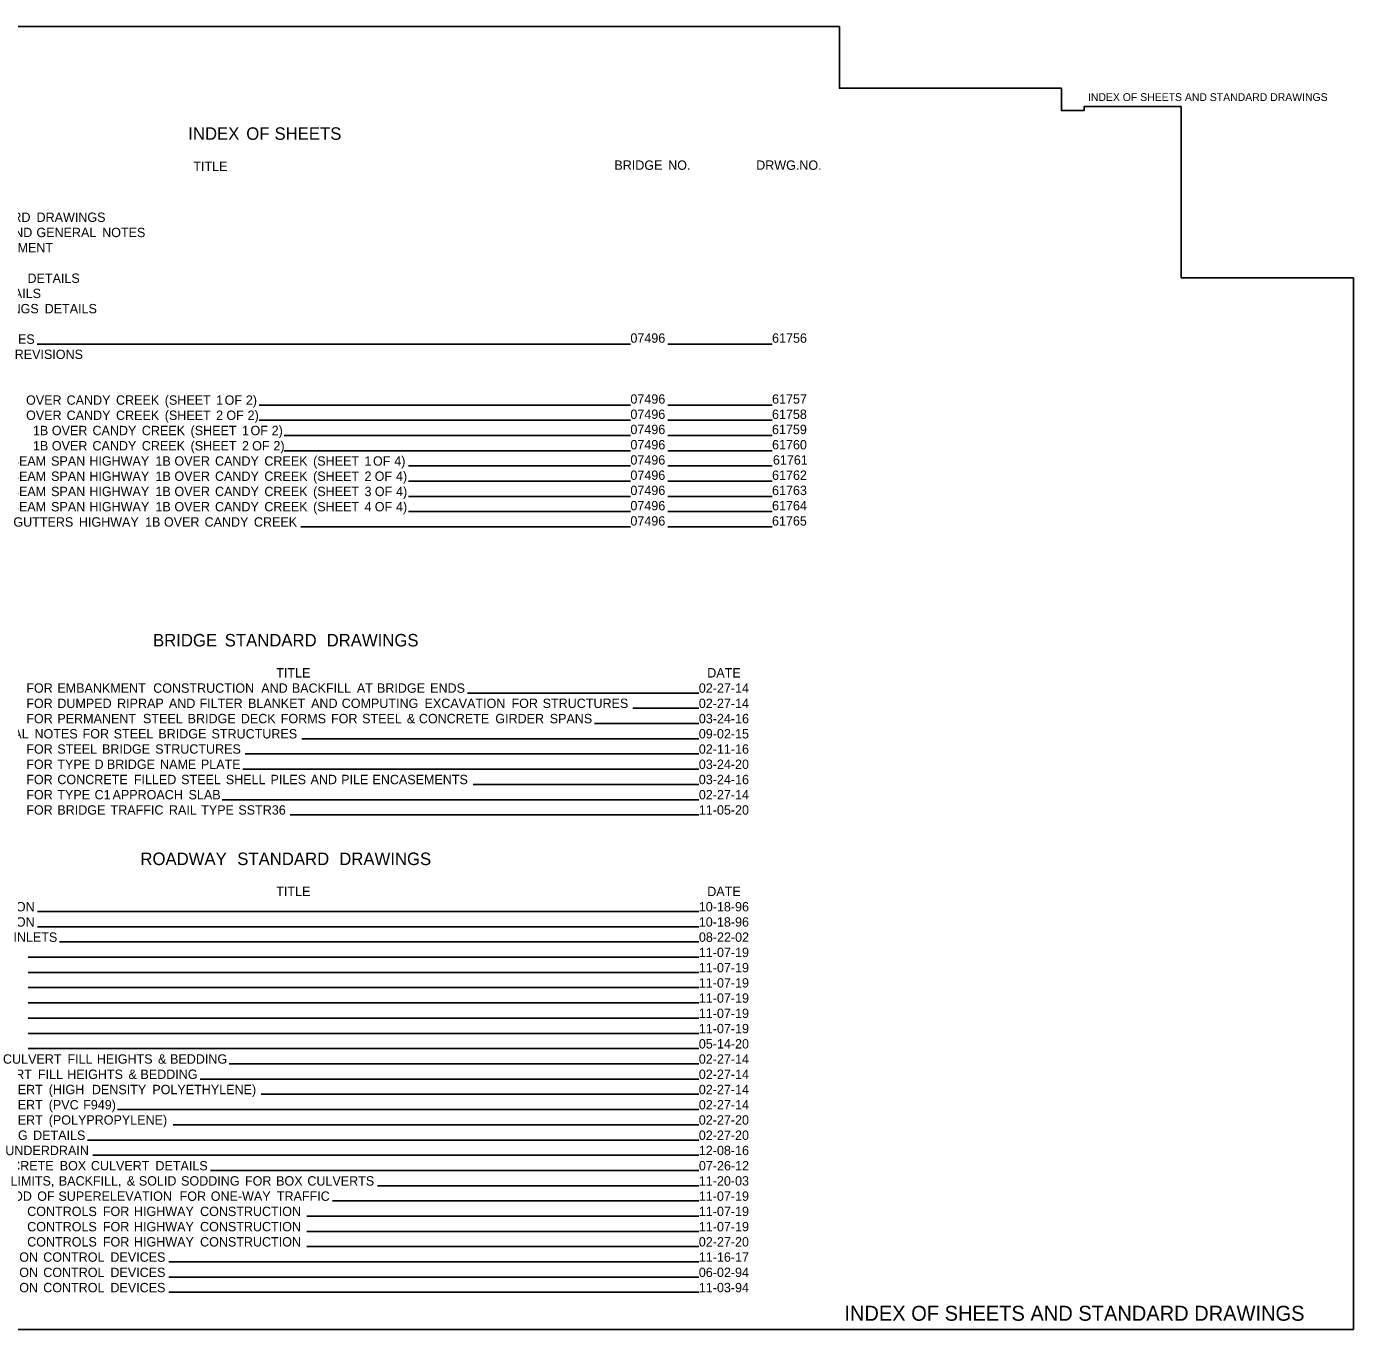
# Model space of a CAD drawing. Extents: x 1955683 to 1956002, y 566394 to 566602.
# Drawn here: x 1955790.1 to 1956002.5, y 566393.5 to 566602 of the extents above; entities that cross this region are included whole.
import ezdxf

# ---------------------------------------------------------------- set-up
doc = ezdxf.new("R2010")
doc.units = 0
for name, color, linetype in [('Default', 7, 'Continuous'), ('R_Border', 7, 'Continuous'), ('R_Border Prem', 7, 'Continuous'), ('STAMP', 7, 'Continuous')]:
    doc.layers.add(name, color=color, linetype=linetype)

msp = doc.modelspace()

# ---------------------------------------------------------------- linework, layer by layer
at = {"layer": 'Default'}
for p, q in [((1955791.8, 566551.17), (1955886.73, 566551.17)), ((1955892.72, 566551.17), (1955909.4, 566551.17)), ((1955827.32, 566541.42), (1955886.73, 566541.42)), ((1955892.72, 566541.42), (1955909.4, 566541.42)), ((1955827.32, 566538.98), (1955886.73, 566538.98)), ((1955892.72, 566538.98), (1955909.4, 566538.98)), ((1955831.34, 566536.54), (1955886.73, 566536.54)), ((1955892.72, 566536.54), (1955909.4, 566536.54)), ((1955831.34, 566534.11), (1955886.73, 566534.11)), ((1955892.72, 566534.11), (1955909.4, 566534.11)), ((1955851.21, 566531.67), (1955886.73, 566531.67)), ((1955892.72, 566531.67), (1955909.4, 566531.67)), ((1955851.21, 566529.23), (1955886.73, 566529.23)), ((1955892.72, 566529.23), (1955909.4, 566529.23)), ((1955851.21, 566526.79), (1955886.73, 566526.79)), ((1955892.72, 566526.79), (1955909.4, 566526.79)), ((1955851.21, 566524.36), (1955886.73, 566524.36)), ((1955892.72, 566524.36), (1955909.4, 566524.36)), ((1955833.98, 566521.92), (1955886.73, 566521.92)), ((1955892.72, 566521.92), (1955909.4, 566521.92)), ((1955860.67, 566495.34), (1955897.68, 566495.34)), ((1955887.13, 566492.9), (1955897.68, 566492.9)), ((1955880.97, 566490.46), (1955897.68, 566490.46)), ((1955834.13, 566488.02), (1955897.68, 566488.02)), ((1955825.06, 566485.59), (1955897.68, 566485.59)), ((1955824.68, 566483.15), (1955897.68, 566483.15)), ((1955861.56, 566480.71), (1955897.68, 566480.71)), ((1955821.37, 566478.27), (1955897.68, 566478.27)), ((1955832.26, 566475.84), (1955897.68, 566475.84)), ((1955791.86, 566460.38), (1955897.68, 566460.38)), ((1955791.86, 566457.95), (1955897.68, 566457.95)), ((1955795.37, 566455.51), (1955897.68, 566455.51)), ((1955790.32, 566453.07), (1955897.68, 566453.07)), ((1955790.32, 566450.63), (1955897.68, 566450.63)), ((1955790.32, 566448.2), (1955897.68, 566448.2)), ((1955790.32, 566445.76), (1955897.68, 566445.76)), ((1955790.32, 566443.32), (1955897.68, 566443.32)), ((1955790.32, 566440.88), (1955897.68, 566440.88)), ((1955790.32, 566438.45), (1955897.68, 566438.45)), ((1955822.5, 566436.01), (1955897.68, 566436.01)), ((1955817.88, 566433.57), (1955897.68, 566433.57)), ((1955827.64, 566431.13), (1955897.68, 566431.13)), ((1955804.62, 566428.7), (1955897.68, 566428.7)), ((1955813.53, 566426.26), (1955897.68, 566426.26)), ((1955799.86, 566423.82), (1955897.68, 566423.82)), ((1955800.72, 566421.38), (1955897.68, 566421.38)), ((1955819.54, 566418.95), (1955897.68, 566418.95)), ((1955846.27, 566416.51), (1955897.68, 566416.51)), ((1955839.05, 566414.07), (1955897.68, 566414.07)), ((1955834.97, 566411.63), (1955897.68, 566411.63)), ((1955834.97, 566409.2), (1955897.68, 566409.2)), ((1955834.97, 566406.76), (1955897.68, 566406.76)), ((1955812.84, 566404.32), (1955897.68, 566404.32)), ((1955812.84, 566401.88), (1955897.68, 566401.88)), ((1955812.84, 566399.45), (1955897.68, 566399.45))]:
    msp.add_line(p, q, dxfattribs=at)
at = {"layer": 'R_Border Prem'}
for points in [[(1956002.45, 566561.79), (1956002.45, 566393.51), (1955683.38, 566393.51), (1955683.38, 566601.97), (1955920.19, 566601.97), (1955920.19, 566592.09), (1955955.71, 566592.09), (1955955.71, 566588.52), (1955959.35, 566588.52), (1955959.35, 566589.17), (1955974.89, 566589.17)], [(1955974.89, 566589.17), (1955974.89, 566561.79), (1956002.45, 566561.79)]]:
    msp.add_lwpolyline(points, dxfattribs=at)

# ---------------------------------------------------------------- texts
at = {"layer": 'Default'}
for s, height, p in [('INDEX', 2, (1955815.97, 566583.85)), (' OF', 2, (1955824.51, 566583.85)), (' SHEETS', 2, (1955829.03, 566583.85)), ('BRIDGE', 1.5, (1955884.17, 566579.05)), (' NO.', 1.5, (1955892.22, 566579.05)), ('DRWG.NO.', 1.5, (1955906.86, 566579.05)), ('TITLE', 1.5, (1955816.78, 566578.88)), (' STANDARD', 1.5, (1955779.13, 566570.71)), (' DRAWINGS', 1.5, (1955791.13, 566570.71)), (' AND', 1.5, (1955786.21, 566568.28)), (' GENERAL', 1.5, (1955791.11, 566568.28)), (' NOTES', 1.5, (1955801.63, 566568.28)), (' IMPROVEMENT', 1.5, (1955778.84, 566565.84)), (' DETAILS', 1.5, (1955789.68, 566560.96)), (' DETAILS', 1.5, (1955783.48, 566558.53)), (' MARKINGS', 1.5, (1955780.78, 566556.09)), (' DETAILS', 1.5, (1955792.43, 566556.09)), ('07496', 1.5, (1955886.73, 566551.38)), ('61756', 1.5, (1955909.4, 566551.38)), (' QUANTITIES', 1.5, (1955778.8, 566551.21)), (' REVISIONS', 1.5, (1955787.63, 566548.78)), (' OVER', 1.5, (1955789.45, 566541.46)), (' CANDY', 1.5, (1955795.94, 566541.46)), (' CREEK', 1.5, (1955803.85, 566541.46)), (' (SHEET', 1.5, (1955811.65, 566541.46)), (' 1', 1.5, (1955819.87, 566541.46)), (' OF', 1.5, (1955821.23, 566541.46)), (' 2)', 1.5, (1955824.63, 566541.46)), ('07496', 1.5, (1955886.73, 566541.63)), ('61757', 1.5, (1955909.4, 566541.63)), (' OVER', 1.5, (1955789.45, 566539.03)), (' CANDY', 1.5, (1955795.94, 566539.03)), (' CREEK', 1.5, (1955803.85, 566539.03)), (' (SHEET', 1.5, (1955811.65, 566539.03)), (' 2', 1.5, (1955819.87, 566539.03)), (' OF', 1.5, (1955821.51, 566539.03)), (' 2)', 1.5, (1955824.91, 566539.03)), ('07496', 1.5, (1955886.73, 566539.19)), ('61758', 1.5, (1955909.39, 566539.19)), (' 1B', 1.5, (1955790.55, 566536.59)), (' OVER', 1.5, (1955793.58, 566536.59)), (' CANDY', 1.5, (1955800.08, 566536.59)), (' CREEK', 1.5, (1955807.98, 566536.59)), (' (SHEET', 1.5, (1955815.78, 566536.59)), (' 1', 1.5, (1955824.01, 566536.59)), (' OF', 1.5, (1955825.37, 566536.59)), (' 2)', 1.5, (1955828.76, 566536.59)), ('07496', 1.5, (1955886.73, 566536.76)), ('61759', 1.5, (1955909.39, 566536.76)), (' 1B', 1.5, (1955790.55, 566534.15)), (' OVER', 1.5, (1955793.58, 566534.15)), (' CANDY', 1.5, (1955800.08, 566534.15)), (' CREEK', 1.5, (1955807.98, 566534.15)), (' (SHEET', 1.5, (1955815.78, 566534.15)), (' 2', 1.5, (1955824.01, 566534.15)), (' OF', 1.5, (1955825.64, 566534.15)), (' 2)', 1.5, (1955829.04, 566534.15)), ('07496', 1.5, (1955886.73, 566534.32)), ('61760', 1.5, (1955909.4, 566534.32)), (' W-BEAM', 1.5, (1955784.42, 566531.71)), (' SPAN', 1.5, (1955793.46, 566531.71)), (' HIGHWAY', 1.5, (1955799.58, 566531.71)), (' 1B', 1.5, (1955810.16, 566531.71)), (' OVER', 1.5, (1955813.2, 566531.71)), (' CANDY', 1.5, (1955819.69, 566531.71)), (' CREEK', 1.5, (1955827.59, 566531.71)), (' (SHEET', 1.5, (1955835.39, 566531.71)), (' 1', 1.5, (1955843.62, 566531.71)), (' OF', 1.5, (1955844.98, 566531.71)), (' 4)', 1.5, (1955848.38, 566531.71)), ('07496', 1.5, (1955886.73, 566531.88)), ('61761', 1.5, (1955909.54, 566531.88)), (' W-BEAM', 1.5, (1955784.42, 566529.28)), (' SPAN', 1.5, (1955793.46, 566529.28)), (' HIGHWAY', 1.5, (1955799.58, 566529.28)), (' 1B', 1.5, (1955810.16, 566529.28)), (' OVER', 1.5, (1955813.2, 566529.28)), (' CANDY', 1.5, (1955819.69, 566529.28)), (' CREEK', 1.5, (1955827.59, 566529.28)), (' (SHEET', 1.5, (1955835.39, 566529.28)), (' 2', 1.5, (1955843.62, 566529.28)), (' OF', 1.5, (1955845.25, 566529.28)), (' 4)', 1.5, (1955848.65, 566529.28)), ('07496', 1.5, (1955886.73, 566529.44)), ('61762', 1.5, (1955909.4, 566529.44)), (' W-BEAM', 1.5, (1955784.42, 566526.84)), (' SPAN', 1.5, (1955793.46, 566526.84)), (' HIGHWAY', 1.5, (1955799.58, 566526.84)), (' 1B', 1.5, (1955810.16, 566526.84)), (' OVER', 1.5, (1955813.2, 566526.84)), (' CANDY', 1.5, (1955819.69, 566526.84)), (' CREEK', 1.5, (1955827.59, 566526.84)), (' (SHEET', 1.5, (1955835.39, 566526.84)), (' 3', 1.5, (1955843.62, 566526.84)), (' OF', 1.5, (1955845.27, 566526.84)), (' 4)', 1.5, (1955848.67, 566526.84)), ('07496', 1.5, (1955886.73, 566527.01)), ('61763', 1.5, (1955909.4, 566527.01)), (' W-BEAM', 1.5, (1955784.42, 566524.4)), (' SPAN', 1.5, (1955793.46, 566524.4)), (' HIGHWAY', 1.5, (1955799.58, 566524.4)), (' 1B', 1.5, (1955810.16, 566524.4)), (' OVER', 1.5, (1955813.2, 566524.4)), (' CANDY', 1.5, (1955819.69, 566524.4)), (' CREEK', 1.5, (1955827.59, 566524.4)), (' (SHEET', 1.5, (1955835.39, 566524.4)), (' 4', 1.5, (1955843.62, 566524.4)), (' OF', 1.5, (1955845.26, 566524.4)), (' 4)', 1.5, (1955848.66, 566524.4)), ('07496', 1.5, (1955886.73, 566524.57)), ('61764', 1.5, (1955909.4, 566524.57)), (' GUTTERS', 1.5, (1955787.42, 566521.96)), (' HIGHWAY', 1.5, (1955797.91, 566521.96)), (' 1B', 1.5, (1955808.49, 566521.96)), (' OVER', 1.5, (1955811.52, 566521.96)), (' CANDY', 1.5, (1955818.02, 566521.96)), (' CREEK', 1.5, (1955825.92, 566521.96)), ('07496', 1.5, (1955886.73, 566522.13)), ('61765', 1.5, (1955909.39, 566522.13)), ('BRIDGE', 2, (1955810.33, 566502.79)), (' STANDARD', 2, (1955821.06, 566502.79)), (' DRAWINGS', 2, (1955837.37, 566502.79)), ('TITLE', 1.5, (1955830.05, 566497.82)), ('DATE', 1.5, (1955899.03, 566497.82)), (' FOR', 1.5, (1955789.49, 566495.38)), (' EMBANKMENT', 1.5, (1955794.46, 566495.38)), (' CONSTRUCTION', 1.5, (1955809.8, 566495.38)), (' AND', 1.5, (1955827.09, 566495.38)), (' BACKFILL', 1.5, (1955831.99, 566495.38)), (' AT', 1.5, (1955842.39, 566495.38)), (' BRIDGE', 1.5, (1955845.61, 566495.38)), (' ENDS', 1.5, (1955854.12, 566495.38)), ('02-27-14', 1.5, (1955897.68, 566495.38)), (' FOR', 1.5, (1955789.49, 566492.94)), (' DUMPED', 1.5, (1955794.46, 566492.94)), (' RIPRAP', 1.5, (1955804.02, 566492.94)), (' AND', 1.5, (1955812.31, 566492.94)), (' FILTER', 1.5, (1955817.21, 566492.94)), (' BLANKET', 1.5, (1955824.98, 566492.94)), (' AND', 1.5, (1955835.07, 566492.94)), (' COMPUTING', 1.5, (1955839.97, 566492.94)), (' EXCAVATION', 1.5, (1955853.23, 566492.94)), (' FOR', 1.5, (1955867.15, 566492.94)), (' STRUCTURES', 1.5, (1955872.13, 566492.94)), ('02-27-14', 1.5, (1955897.68, 566492.94)), (' FOR', 1.5, (1955789.49, 566490.5)), (' PERMANENT', 1.5, (1955794.46, 566490.5)), (' STEEL', 1.5, (1955808.16, 566490.5)), (' BRIDGE', 1.5, (1955815.31, 566490.5)), (' DECK', 1.5, (1955823.82, 566490.5)), (' FORMS', 1.5, (1955830.22, 566490.5)), (' FOR', 1.5, (1955838.26, 566490.5)), (' STEEL', 1.5, (1955843.24, 566490.5)), (' &', 1.5, (1955850.39, 566490.5)), (' CONCRETE', 1.5, (1955852.32, 566490.5)), (' GIRDER', 1.5, (1955864.55, 566490.5)), (' SPANS', 1.5, (1955873.26, 566490.5)), ('03-24-16', 1.5, (1955897.68, 566490.5)), (' GENERAL', 1.5, (1955780.28, 566488.07)), (' NOTES', 1.5, (1955790.8, 566488.07)), (' FOR', 1.5, (1955798.5, 566488.07)), (' STEEL', 1.5, (1955803.48, 566488.07)), (' BRIDGE', 1.5, (1955810.62, 566488.07)), (' STRUCTURES', 1.5, (1955819.13, 566488.07)), ('09-02-15', 1.5, (1955897.68, 566488.07)), (' FOR', 1.5, (1955789.49, 566485.63)), (' STEEL', 1.5, (1955794.46, 566485.63)), (' BRIDGE', 1.5, (1955801.61, 566485.63)), (' STRUCTURES', 1.5, (1955810.12, 566485.63)), ('02-11-16', 1.5, (1955897.68, 566485.63)), (' FOR', 1.5, (1955789.49, 566483.19)), (' TYPE', 1.5, (1955794.46, 566483.19)), (' D', 1.5, (1955800.41, 566483.19)), (' BRIDGE', 1.5, (1955802.39, 566483.19)), (' NAME', 1.5, (1955810.9, 566483.19)), (' PLATE', 1.5, (1955817.43, 566483.19)), ('03-24-20', 1.5, (1955897.68, 566483.19)), (' FOR', 1.5, (1955789.49, 566480.75)), (' CONCRETE', 1.5, (1955794.46, 566480.75)), (' FILLED', 1.5, (1955806.7, 566480.75)), (' STEEL', 1.5, (1955814.27, 566480.75)), (' SHELL', 1.5, (1955821.42, 566480.75)), (' PILES', 1.5, (1955828.57, 566480.75)), (' AND', 1.5, (1955834.98, 566480.75)), (' PILE', 1.5, (1955839.88, 566480.75)), (' ENCASEMENTS', 1.5, (1955844.89, 566480.75)), ('03-24-16', 1.5, (1955897.68, 566480.75)), (' FOR', 1.5, (1955789.49, 566478.32)), (' TYPE', 1.5, (1955794.46, 566478.32)), (' C1', 1.5, (1955800.41, 566478.32)), (' APPROACH', 1.5, (1955803.29, 566478.32)), (' SLAB', 1.5, (1955815.46, 566478.32)), ('02-27-14', 1.5, (1955897.68, 566478.32)), (' FOR', 1.5, (1955789.49, 566475.88)), (' BRIDGE', 1.5, (1955794.46, 566475.88)), (' TRAFFIC', 1.5, (1955802.97, 566475.88)), (' RAIL', 1.5, (1955812.32, 566475.88)), (' TYPE', 1.5, (1955817.48, 566475.88)), (' SSTR36', 1.5, (1955823.43, 566475.88)), ('11-05-20', 1.5, (1955897.68, 566475.88)), ('ROADWAY', 2, (1955808.31, 566467.81)), (' STANDARD', 2, (1955823.07, 566467.81)), (' DRAWINGS', 2, (1955839.39, 566467.81)), ('TITLE', 1.5, (1955830.05, 566462.84)), ('DATE', 1.5, (1955899.03, 566462.84)), (' SECTION', 1.5, (1955781.91, 566460.4)), ('10-18-96', 1.5, (1955897.68, 566460.4)), (' SECTION', 1.5, (1955781.91, 566457.96)), ('10-18-96', 1.5, (1955897.68, 566457.96)), (' INLETS', 1.5, (1955787.43, 566455.53)), ('08-22-02', 1.5, (1955897.69, 566455.53)), ('11-07-19', 1.5, (1955897.68, 566453.09)), ('11-07-19', 1.5, (1955897.68, 566450.65)), ('11-07-19', 1.5, (1955897.68, 566448.21)), ('11-07-19', 1.5, (1955897.68, 566445.78)), ('11-07-19', 1.5, (1955897.68, 566443.34)), ('11-07-19', 1.5, (1955897.68, 566440.9)), ('05-14-20', 1.5, (1955897.68, 566438.46)), (' CULVERT', 1.5, (1955785.76, 566436.03)), (' FILL', 1.5, (1955796.08, 566436.03)), (' HEIGHTS', 1.5, (1955800.78, 566436.03)), (' &', 1.5, (1955810.57, 566436.03)), (' BEDDING', 1.5, (1955812.5, 566436.03)), ('02-27-14', 1.5, (1955897.68, 566436.03)), (' CULVERT', 1.5, (1955781.02, 566433.59)), (' FILL', 1.5, (1955791.34, 566433.59)), (' HEIGHTS', 1.5, (1955796.04, 566433.59)), (' &', 1.5, (1955805.83, 566433.59)), (' BEDDING', 1.5, (1955807.76, 566433.59)), ('02-27-14', 1.5, (1955897.68, 566433.59)), (' CULVERT', 1.5, (1955782.76, 566431.15)), (' (HIGH', 1.5, (1955793.08, 566431.15)), ('  DENSITY', 1.5, (1955799.43, 566431.15)), (' POLYETHYLENE)', 1.5, (1955809.66, 566431.15)), ('02-27-14', 1.5, (1955897.68, 566431.15)), (' CULVERT', 1.5, (1955782.76, 566428.71)), (' (PVC', 1.5, (1955793.08, 566428.71)), (' F949)', 1.5, (1955798.59, 566428.71)), ('02-27-14', 1.5, (1955897.68, 566428.71)), (' CULVERT', 1.5, (1955782.76, 566426.28)), (' (POLYPROPYLENE)', 1.5, (1955793.08, 566426.28)), ('02-27-20', 1.5, (1955897.68, 566426.28)), (' MARKING', 1.5, (1955780.35, 566423.84)), (' DETAILS', 1.5, (1955790.58, 566423.84)), ('02-27-20', 1.5, (1955897.68, 566423.84)), (' UNDERDRAIN', 1.5, (1955786.13, 566421.4)), ('12-08-16', 1.5, (1955897.68, 566421.4)), (' CONCRETE', 1.5, (1955782.61, 566418.96)), (' BOX', 1.5, (1955794.84, 566418.96)), (' CULVERT', 1.5, (1955799.83, 566418.96)), (' DETAILS', 1.5, (1955810.16, 566418.96)), ('07-26-12', 1.5, (1955897.69, 566418.96)), (' LIMITS,', 1.5, (1955786.96, 566416.53)), (' BACKFILL,', 1.5, (1955794.69, 566416.53)), (' &', 1.5, (1955805.57, 566416.53)), (' SOLID', 1.5, (1955807.5, 566416.53)), (' SODDING', 1.5, (1955814.26, 566416.53)), (' FOR', 1.5, (1955824.49, 566416.53)), (' BOX', 1.5, (1955829.47, 566416.53)), (' CULVERTS', 1.5, (1955834.47, 566416.53)), ('11-20-03', 1.5, (1955897.68, 566416.53)), (' METHOD', 1.5, (1955781.69, 566414.09)), (' OF', 1.5, (1955791.24, 566414.09)), (' SUPERELEVATION', 1.5, (1955794.63, 566414.09)), (' FOR', 1.5, (1955814.03, 566414.09)), (' ONE-WAY', 1.5, (1955819.01, 566414.09)), (' TRAFFIC', 1.5, (1955829.59, 566414.09)), ('11-07-19', 1.5, (1955897.68, 566414.09)), (' CONTROLS', 1.5, (1955789.63, 566411.65)), (' FOR', 1.5, (1955801.74, 566411.65)), (' HIGHWAY', 1.5, (1955806.72, 566411.65)), (' CONSTRUCTION', 1.5, (1955817.3, 566411.65)), ('11-07-19', 1.5, (1955897.68, 566411.65)), (' CONTROLS', 1.5, (1955789.63, 566409.21)), (' FOR', 1.5, (1955801.74, 566409.21)), (' HIGHWAY', 1.5, (1955806.72, 566409.21)), (' CONSTRUCTION', 1.5, (1955817.3, 566409.21)), ('11-07-19', 1.5, (1955897.68, 566409.21)), (' CONTROLS', 1.5, (1955789.63, 566406.78)), (' FOR', 1.5, (1955801.74, 566406.78)), (' HIGHWAY', 1.5, (1955806.72, 566406.78)), (' CONSTRUCTION', 1.5, (1955817.3, 566406.78)), ('02-27-20', 1.5, (1955897.68, 566406.78)), (' EROSION', 1.5, (1955782.12, 566404.34)), (' CONTROL', 1.5, (1955792.2, 566404.34)), (' DEVICES', 1.5, (1955802.95, 566404.34)), ('11-16-17', 1.5, (1955897.68, 566404.34)), (' EROSION', 1.5, (1955782.12, 566401.9)), (' CONTROL', 1.5, (1955792.2, 566401.9)), (' DEVICES', 1.5, (1955802.95, 566401.9)), ('06-02-94', 1.5, (1955897.68, 566401.9)), (' EROSION', 1.5, (1955782.12, 566399.46)), (' CONTROL', 1.5, (1955792.2, 566399.46)), (' DEVICES', 1.5, (1955802.95, 566399.46)), ('11-03-94', 1.5, (1955897.68, 566399.46))]:
    msp.add_text(s, height=height, dxfattribs=at).set_placement(p)
at = {"layer": 'R_Border'}
msp.add_text('INDEX OF SHEETS AND STANDARD DRAWINGS', height=2.4, rotation=0, dxfattribs=at).set_placement((1955920.97, 566394.9))
at = {"layer": 'STAMP'}
msp.add_text('INDEX OF SHEETS AND STANDARD DRAWINGS', height=1.25, rotation=360, dxfattribs=at).set_placement((1955959.96, 566590.06))

doc.saveas('drawing.dxf')
